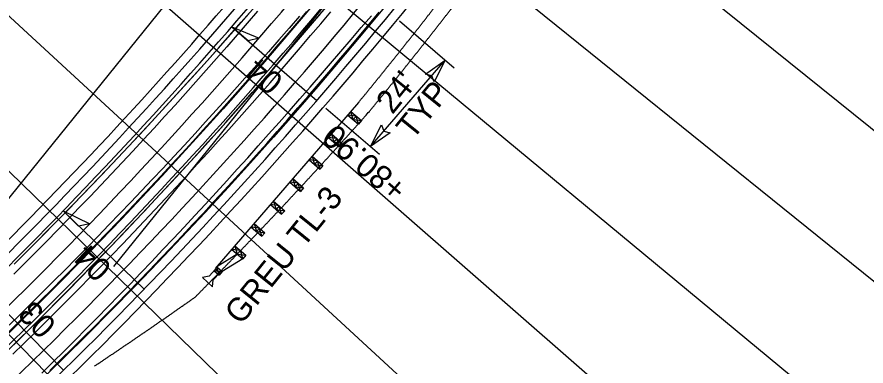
# Model space of a CAD drawing. Extents: x 2293233 to 2294507, y 892788 to 894229.
# Drawn here: x 2293687.7 to 2293868.5, y 893239.9 to 893314.3 of the extents above; entities that cross this region are included whole.
import ezdxf

# ---------------------------------------------------------------- set-up
doc = ezdxf.new("R2010")
doc.units = 0
for name, color, linetype in [('COGO Default Curve', 7, 'Continuous'), ('Prop Dimension', 7, 'Continuous'), ('Prop EOT', 7, 'Continuous'), ('Prop Guardrail', 7, 'Continuous'), ('Prop Guardrail Anchor Unit CELL', 7, 'Continuous'), ('Prop Horizontal Alignment', 7, 'Continuous'), ('Prop Paved Shoulder', 7, 'Continuous'), ('Prop Superelevation  Arrow CELL', 7, 'Continuous'), ('Prop Superelevation Label', 7, 'Continuous'), ('Scratch_Level_4', 7, 'Continuous'), ('Scratch_Level_5', 7, 'Continuous'), ('Typical Terminator CELL', 7, 'Continuous')]:
    doc.layers.add(name, color=color, linetype=linetype)

# ---------------------------------------------------------------- blocks, each defined once
blk = doc.blocks.new('TERMINATOR')
at = {"layer": 'Typical Terminator CELL'}
blk.add_lwpolyline([(-0.469, 0.081), (0, 0), (-0.471, -0.083), (-0.411, 0)], close=True, dxfattribs=at)

msp = doc.modelspace()

# ---------------------------------------------------------------- linework, layer by layer
at = {"layer": 'COGO Default Curve'}
for points in [[(2294073.94, 893697.86), (2293868.79, 893443.63), (2293792.2, 893348.66), (2293779.83, 893333.36), (2293770.79, 893322.25), (2293765.29, 893315.55), (2293760.6, 893309.91), (2293756.09, 893304.55), (2293751.76, 893299.48), (2293746.96, 893293.94), (2293742.34, 893288.69), (2293737.45, 893283.22), (2293732.75, 893278.03), (2293727.78, 893272.64), (2293722.77, 893267.28), (2293717.72, 893261.96), (2293712.86, 893256.92), (2293707.73, 893251.68), (2293702.8, 893246.71), (2293697.59, 893241.55), (2293692.58, 893236.66)], [(2294044.74, 893680.7), (2293954.06, 893568.41), (2293770.67, 893341.16), (2293761.43, 893329.77), (2293756.77, 893324.11), (2293752.51, 893318.98), (2293748.22, 893313.88), (2293744.11, 893309.05), (2293739.98, 893304.26), (2293735.81, 893299.49), (2293731.62, 893294.74), (2293727.39, 893290.03), (2293722.91, 893285.09), (2293718.62, 893280.44), (2293714.3, 893275.81), (2293709.95, 893271.21), (2293705.56, 893266.64), (2293701.15, 893262.1), (2293696.71, 893257.59), (2293692.23, 893253.11), (2293687.73, 893248.66), (2293683.19, 893244.24), (2293678.63, 893239.85)], [(2293680.14, 893237.74), (2293686.34, 893243.78), (2293692.26, 893249.64), (2293698.14, 893255.55), (2293703.96, 893261.51), (2293709.74, 893267.51), (2293715.47, 893273.56), (2293720.92, 893279.42), (2293726.55, 893285.56), (2293732.12, 893291.75), (2293737.87, 893298.24), (2293743.8, 893305.01), (2293749.89, 893312.08), (2293756.38, 893319.69), (2293763.26, 893327.84), (2293770.53, 893336.54), (2293778.4, 893346.03), (2293786.88, 893356.32), (2293796.39, 893367.93), (2293808.61, 893382.91), (2293822.69, 893400.24), (2293860.23, 893446.62), (2293932.89, 893536.61), (2294046.75, 893677.72)], [(2293687.14, 893261.63), (2293692.08, 893266.58), (2293696.99, 893271.57), (2293701.87, 893276.59), (2293706.71, 893281.65), (2293711.51, 893286.74), (2293716.29, 893291.86), (2293721.02, 893297.02), (2293725.73, 893302.2), (2293730.62, 893307.66), (2293735.48, 893313.16), (2293740.31, 893318.68), (2293745.1, 893324.23), (2293750.07, 893330.06), (2293755.02, 893335.92), (2293760.15, 893342.06), (2293765.46, 893348.48), (2293771.17, 893355.44), (2293778.96, 893365), (2293789.02, 893377.44), (2293934.91, 893558.24), (2293982.19, 893616.89)], [(2293749.37, 893315.47), (2293747.21, 893312.92), (2293745.05, 893310.37), (2293742.87, 893307.83), (2293740.69, 893305.29), (2293738.49, 893302.76), (2293736.29, 893300.25), (2293734.08, 893297.73), (2293731.85, 893295.23), (2293729.62, 893292.73), (2293727.38, 893290.24), (2293725.14, 893287.76), (2293722.88, 893285.29), (2293720.61, 893282.82), (2293718.34, 893280.37), (2293716.06, 893277.92), (2293713.76, 893275.48), (2293711.46, 893273.04), (2293709.16, 893270.62), (2293706.84, 893268.2), (2293704.51, 893265.79), (2293702.18, 893263.39), (2293699.83, 893261), (2293697.48, 893258.62), (2293695.12, 893256.24), (2293692.75, 893253.87), (2293690.38, 893251.51), (2293687.99, 893249.16), (2293685.6, 893246.82)], [(2293686.81, 893242.42), (2293689.19, 893244.74), (2293691.56, 893247.06), (2293693.92, 893249.39), (2293696.28, 893251.74), (2293698.62, 893254.08), (2293700.96, 893256.44), (2293703.29, 893258.81), (2293705.61, 893261.18), (2293707.92, 893263.56), (2293710.23, 893265.95), (2293712.52, 893268.35), (2293714.81, 893270.76), (2293717.09, 893273.17), (2293719.36, 893275.59), (2293721.62, 893278.02), (2293723.88, 893280.46), (2293726.12, 893282.91), (2293728.36, 893285.36), (2293730.59, 893287.82), (2293732.81, 893290.29), (2293735.02, 893292.76), (2293737.22, 893295.25), (2293739.41, 893297.74), (2293741.6, 893300.24), (2293743.77, 893302.75), (2293745.94, 893305.26), (2293748.1, 893307.78), (2293750.25, 893310.31), (2293752.39, 893312.85), (2293754.52, 893315.4)], [(2293738.9, 893315.49), (2293736.74, 893312.96), (2293734.57, 893310.45), (2293732.39, 893307.94), (2293730.2, 893305.44), (2293728.01, 893302.95), (2293725.8, 893300.46), (2293723.59, 893297.98), (2293721.37, 893295.52), (2293719.14, 893293.05), (2293716.9, 893290.6), (2293714.65, 893288.16), (2293712.39, 893285.72), (2293710.13, 893283.29), (2293707.86, 893280.87), (2293705.58, 893278.46), (2293703.29, 893276.05), (2293700.99, 893273.66), (2293698.68, 893271.27), (2293696.36, 893268.89), (2293694.04, 893266.52), (2293691.71, 893264.15), (2293689.37, 893261.8), (2293687.02, 893259.45)], [(2293687.02, 893244.44), (2293689.38, 893246.77), (2293691.73, 893249.11), (2293694.08, 893251.46), (2293696.41, 893253.81), (2293698.74, 893256.17), (2293701.07, 893258.53), (2293703.38, 893260.91), (2293705.69, 893263.29), (2293707.99, 893265.68), (2293710.28, 893268.07), (2293712.56, 893270.48), (2293714.84, 893272.89), (2293717.1, 893275.31), (2293719.36, 893277.74), (2293721.61, 893280.17), (2293723.86, 893282.61), (2293726.09, 893285.06), (2293728.32, 893287.52), (2293730.54, 893289.98), (2293732.75, 893292.46), (2293734.96, 893294.93), (2293737.15, 893297.42), (2293739.35, 893299.91), (2293741.53, 893302.41), (2293743.71, 893304.92), (2293745.89, 893307.43), (2293748.06, 893309.95), (2293750.22, 893312.47), (2293752.39, 893314.99)], [(2293737.08, 893314.98), (2293734.89, 893312.49), (2293732.7, 893310), (2293730.49, 893307.52), (2293728.28, 893305.04), (2293726.06, 893302.57), (2293723.84, 893300.11), (2293721.61, 893297.66), (2293719.37, 893295.21), (2293717.12, 893292.77), (2293714.87, 893290.33), (2293712.6, 893287.91), (2293710.34, 893285.49), (2293708.06, 893283.07), (2293705.77, 893280.67), (2293703.48, 893278.27), (2293701.18, 893275.88), (2293698.87, 893273.5), (2293696.56, 893271.13), (2293694.23, 893268.76), (2293691.9, 893266.4), (2293689.56, 893264.05), (2293687.22, 893261.71)], [(2293694.69, 893238.93), (2293697.08, 893241.27), (2293699.46, 893243.62), (2293701.84, 893245.98), (2293704.2, 893248.35), (2293706.56, 893250.73), (2293708.91, 893253.12), (2293711.25, 893255.51), (2293713.58, 893257.91), (2293715.91, 893260.32), (2293718.22, 893262.74), (2293720.53, 893265.16), (2293722.83, 893267.6), (2293725.12, 893270.04), (2293727.4, 893272.49), (2293729.67, 893274.95), (2293731.94, 893277.41), (2293734.19, 893279.89), (2293736.44, 893282.37), (2293738.68, 893284.86), (2293740.91, 893287.35), (2293743.13, 893289.86), (2293745.34, 893292.37), (2293747.55, 893294.89), (2293749.74, 893297.42), (2293751.93, 893299.95), (2293754.1, 893302.5), (2293756.27, 893305.05), (2293758.43, 893307.61), (2293760.58, 893310.17), (2293762.72, 893312.74), (2293764.86, 893315.33)], [(2293747.87, 893314.43), (2293745.68, 893311.9), (2293743.48, 893309.39), (2293741.27, 893306.87), (2293739.06, 893304.37), (2293736.84, 893301.87), (2293734.61, 893299.37), (2293732.38, 893296.88), (2293730.14, 893294.4), (2293727.89, 893291.93), (2293725.63, 893289.46), (2293723.37, 893287), (2293721.09, 893284.55), (2293718.81, 893282.1), (2293716.53, 893279.66), (2293714.23, 893277.23), (2293711.93, 893274.81), (2293709.62, 893272.39), (2293707.3, 893269.98), (2293704.97, 893267.58), (2293702.63, 893265.18), (2293700.29, 893262.8), (2293697.94, 893260.42), (2293695.58, 893258.05), (2293693.21, 893255.68), (2293690.84, 893253.33), (2293688.46, 893250.98), (2293686.07, 893248.64)], [(2293692.98, 893238.38), (2293695.36, 893240.73), (2293697.73, 893243.09), (2293700.09, 893245.45), (2293702.45, 893247.82), (2293704.8, 893250.2), (2293707.14, 893252.59), (2293709.48, 893254.98), (2293711.8, 893257.38), (2293714.12, 893259.79), (2293716.43, 893262.21), (2293718.73, 893264.63), (2293721.03, 893267.07), (2293723.31, 893269.51), (2293725.59, 893271.95), (2293727.86, 893274.41), (2293730.13, 893276.87), (2293732.38, 893279.34), (2293734.62, 893281.82), (2293736.86, 893284.3), (2293739.09, 893286.8), (2293741.31, 893289.29), (2293743.53, 893291.8), (2293745.74, 893294.31), (2293747.94, 893296.82), (2293750.13, 893299.34), (2293752.32, 893301.87), (2293754.5, 893304.4), (2293756.68, 893306.94), (2293758.85, 893309.47), (2293761.02, 893312.02), (2293763.18, 893314.56)]]:
    msp.add_lwpolyline(points, dxfattribs=at)
for radius in [944, 956]:
    msp.add_arc((2293023.75, 893925.54), radius, 308.6085, 321.09608, dxfattribs=at)
at = {"layer": 'Prop Dimension'}
for p, q in [((2293769.15, 893313.47), (2293780.79, 893303.41)), ((2293763.01, 893286.66), (2293778.89, 893305.05)), ((2293753.49, 893294.88), (2293764.9, 893285.02))]:
    msp.add_line(p, q, dxfattribs=at)
at = {"layer": 'Prop EOT'}
for radius, start in [(938, 309.40221), (962, 308.6085)]:
    msp.add_arc((2293023.75, 893925.54), radius, start, 321.09608, dxfattribs=at)
at = {"layer": 'Prop Guardrail'}
msp.add_spline([(2293760.46, 893296.08), (2293760.89, 893296.61), (2293761.33, 893297.14), (2293761.77, 893297.67), (2293762.2, 893298.21), (2293762.64, 893298.74), (2293763.07, 893299.28), (2293763.51, 893299.81), (2293763.94, 893300.35), (2293764.38, 893300.88), (2293764.81, 893301.42), (2293765.24, 893301.95), (2293765.68, 893302.49), (2293766.11, 893303.03), (2293766.54, 893303.56), (2293766.97, 893304.1), (2293767.41, 893304.64), (2293767.84, 893305.18), (2293768.27, 893305.71), (2293768.7, 893306.25), (2293769.13, 893306.79), (2293769.56, 893307.33), (2293769.99, 893307.87), (2293770.41, 893308.41), (2293770.84, 893308.95), (2293771.27, 893309.49), (2293771.7, 893310.03), (2293772.13, 893310.57), (2293772.55, 893311.11), (2293772.98, 893311.65), (2293773.4, 893312.19), (2293773.83, 893312.74), (2293774.25, 893313.28), (2293774.68, 893313.82), (2293775.1, 893314.36), (2293775.53, 893314.91), (2293775.95, 893315.45), (2293776.37, 893315.99), (2293776.8, 893316.54), (2293777.22, 893317.08), (2293777.64, 893317.62), (2293778.05, 893318.15), (2293778.47, 893318.69), (2293778.88, 893319.22), (2293779.29, 893319.76), (2293779.71, 893320.29), (2293780.12, 893320.83), (2293780.53, 893321.36), (2293780.95, 893321.89), (2293781.36, 893322.43), (2293781.78, 893322.96), (2293782.19, 893323.5), (2293782.6, 893324.03), (2293783.02, 893324.57), (2293783.43, 893325.1), (2293783.84, 893325.63), (2293784.26, 893326.17), (2293784.67, 893326.7), (2293785.09, 893327.24), (2293785.5, 893327.77), (2293785.91, 893328.31), (2293786.33, 893328.84), (2293786.74, 893329.37), (2293787.16, 893329.91), (2293787.57, 893330.44), (2293787.98, 893330.98), (2293788.4, 893331.51), (2293788.81, 893332.05), (2293789.22, 893332.58), (2293789.64, 893333.11), (2293790.05, 893333.65), (2293790.47, 893334.18), (2293790.88, 893334.72), (2293791.29, 893335.25), (2293791.71, 893335.79)], degree=3, dxfattribs=at)
at = {"layer": 'Prop Guardrail Anchor Unit CELL'}
for p, q in [((2293760.46, 893296.08), (2293729.94, 893260.66)), ((2293758.8, 893294.15), (2293758.14, 893293.39)), ((2293758.14, 893293.39), (2293760.42, 893291.43)), ((2293758.14, 893293.39), (2293759.28, 893292.41)), ((2293759.93, 893293.17), (2293758.14, 893293.39)), ((2293758.8, 893294.15), (2293761.07, 893292.19)), ((2293759.28, 893292.41), (2293758.8, 893294.15)), ((2293759.93, 893293.17), (2293759.28, 893292.41)), ((2293760.42, 893291.43), (2293759.93, 893293.17)), ((2293759.28, 893292.41), (2293761.07, 893292.19)), ((2293761.07, 893292.19), (2293760.42, 893291.43)), ((2293754.68, 893289.38), (2293757, 893287.38)), ((2293754.68, 893289.38), (2293755.19, 893287.62)), ((2293754.03, 893288.62), (2293756.34, 893286.63)), ((2293755.84, 893288.38), (2293754.03, 893288.62)), ((2293755.84, 893288.38), (2293755.19, 893287.62)), ((2293755.19, 893287.62), (2293757, 893287.38)), ((2293756.34, 893286.63), (2293755.84, 893288.38)), ((2293757, 893287.38), (2293756.34, 893286.63)), ((2293749.92, 893283.84), (2293752.23, 893281.85)), ((2293751.72, 893283.61), (2293749.92, 893283.84)), ((2293750.57, 893284.6), (2293752.88, 893282.61)), ((2293750.57, 893284.6), (2293751.07, 893282.85)), ((2293751.72, 893283.61), (2293751.07, 893282.85)), ((2293751.07, 893282.85), (2293752.88, 893282.61)), ((2293752.23, 893281.85), (2293751.72, 893283.61)), ((2293752.88, 893282.61), (2293752.23, 893281.85)), ((2293746.46, 893279.83), (2293745.8, 893279.07)), ((2293745.8, 893279.07), (2293748.1, 893277.09)), ((2293747.61, 893278.84), (2293745.8, 893279.07)), ((2293746.46, 893279.83), (2293748.76, 893277.85)), ((2293746.46, 893279.83), (2293746.95, 893278.08)), ((2293747.61, 893278.84), (2293746.95, 893278.08)), ((2293748.1, 893277.09), (2293747.61, 893278.84)), ((2293746.95, 893278.08), (2293748.76, 893277.85)), ((2293748.76, 893277.85), (2293748.1, 893277.09)), ((2293742.34, 893275.05), (2293744.72, 893273.01)), ((2293742.34, 893275.05), (2293742.88, 893273.27)), ((2293741.69, 893274.3), (2293744.07, 893272.25)), ((2293743.53, 893274.03), (2293741.69, 893274.3)), ((2293743.53, 893274.03), (2293742.88, 893273.27)), ((2293742.88, 893273.27), (2293744.72, 893273.01)), ((2293744.07, 893272.25), (2293743.53, 893274.03)), ((2293744.72, 893273.01), (2293744.07, 893272.25)), ((2293737.58, 893269.52), (2293739.85, 893267.56)), ((2293739.37, 893269.3), (2293737.58, 893269.52)), ((2293738.23, 893270.28), (2293740.5, 893268.32)), ((2293738.23, 893270.28), (2293738.72, 893268.54)), ((2293739.37, 893269.3), (2293738.72, 893268.54)), ((2293738.72, 893268.54), (2293740.5, 893268.32)), ((2293739.85, 893267.56), (2293739.37, 893269.3)), ((2293740.5, 893268.32), (2293739.85, 893267.56)), ((2293733.47, 893264.75), (2293735.79, 893262.75)), ((2293735.28, 893264.51), (2293733.47, 893264.75)), ((2293734.12, 893265.51), (2293736.44, 893263.51)), ((2293734.12, 893265.51), (2293734.63, 893263.75)), ((2293735.28, 893264.51), (2293734.63, 893263.75)), ((2293735.79, 893262.75), (2293735.28, 893264.51)), ((2293734.63, 893263.75), (2293730.27, 893261.04)), ((2293735.79, 893262.75), (2293731.4, 893260.06)), ((2293734.63, 893263.75), (2293736.44, 893263.51)), ((2293736.44, 893263.51), (2293735.79, 893262.75)), ((2293729.98, 893260.58), (2293728.61, 893259.06)), ((2293730.43, 893260.18), (2293729.98, 893260.58)), ((2293730.27, 893261.04), (2293731.4, 893260.06)), ((2293730.75, 893259.3), (2293730.27, 893261.04)), ((2293728.61, 893259.06), (2293727.19, 893258.75)), ((2293727.19, 893258.75), (2293729.38, 893256.79)), ((2293729.52, 893258.24), (2293730.89, 893259.77)), ((2293729.61, 893260.28), (2293730.75, 893259.3)), ((2293729.61, 893260.28), (2293731.4, 893260.06)), ((2293730.89, 893259.77), (2293730.43, 893260.18)), ((2293731.4, 893260.06), (2293730.75, 893259.3)), ((2293731.4, 893260.06), (2293731.08, 893259.68)), ((2293729.38, 893256.79), (2293729.52, 893258.24))]:
    msp.add_line(p, q, dxfattribs=at)
at = {"layer": 'Prop Horizontal Alignment'}
msp.add_arc((2293023.75, 893925.54), 950, 308.6085, 321.09608, dxfattribs=at)
msp.add_arc((2293023.75, 893925.54), 950, 308.6085, 321.09608, dxfattribs=at)
at = {"layer": 'Prop Paved Shoulder'}
for radius, start in [(936, 310.01837), (964, 308.6085)]:
    msp.add_arc((2293023.75, 893925.54), radius, start, 321.09608, dxfattribs=at)
at = {"layer": 'Prop Superelevation  Arrow CELL'}
for p, q in [((2293733.44, 893312.21), (2293751.6, 893296.51)), ((2293697.53, 893272.96), (2293714.77, 893256.26)), ((2293680.83, 893256.14), (2293697.64, 893239.02))]:
    msp.add_line(p, q, dxfattribs=at)
for points in [[(2293733.44, 893312.21), (2293739.29, 893309.8), (2293736.94, 893309.18)], [(2293697.53, 893272.96), (2293703.23, 893270.22), (2293700.85, 893269.74)]]:
    msp.add_lwpolyline(points, close=True, dxfattribs=at)
at = {"layer": 'Scratch_Level_4'}
for p, q in [((2293708.32, 893261.12), (2294130.82, 893784.65)), ((2293669.61, 893451.99), (2293903.07, 893263.59)), ((2293653.9, 893432.54), (2293887.36, 893244.13)), ((2293639.43, 893414.71), (2293870.31, 893223.16)), ((2293625.77, 893398.69), (2293851.53, 893201.12)), ((2293611.7, 893383.03), (2293832.18, 893179.59)), ((2293597.22, 893367.75), (2293812.28, 893158.58)), ((2293582.35, 893352.85), (2293791.82, 893138.1))]:
    msp.add_line(p, q, dxfattribs=at)
at = {"layer": 'Scratch_Level_5'}
msp.add_line((2293676.84, 893264.33), (2293818.17, 893439.42), dxfattribs=at)
msp.add_arc((2293023.75, 893925.54), 934, 310.67386, 321.09608, dxfattribs=at)
for points in [[(2293762.77, 893294.17), (2293763.21, 893294.71), (2293763.65, 893295.24), (2293764.09, 893295.78), (2293764.53, 893296.31), (2293764.96, 893296.85), (2293765.4, 893297.38), (2293765.84, 893297.92), (2293766.27, 893298.46), (2293766.71, 893298.99), (2293767.14, 893299.53), (2293767.58, 893300.07), (2293768.01, 893300.61), (2293768.45, 893301.14), (2293768.88, 893301.68), (2293769.31, 893302.22), (2293769.75, 893302.76), (2293770.18, 893303.3), (2293770.61, 893303.84), (2293771.04, 893304.38), (2293771.47, 893304.92), (2293771.9, 893305.46), (2293772.33, 893306), (2293772.76, 893306.54), (2293773.19, 893307.08), (2293773.62, 893307.63), (2293774.05, 893308.17), (2293774.48, 893308.71), (2293774.91, 893309.25), (2293775.34, 893309.8), (2293775.76, 893310.34), (2293776.19, 893310.88), (2293776.62, 893311.43), (2293777.04, 893311.97), (2293777.47, 893312.52), (2293777.89, 893313.06), (2293778.32, 893313.61), (2293778.74, 893314.15), (2293779.17, 893314.7), (2293779.59, 893315.24), (2293780.01, 893315.78), (2293780.42, 893316.32), (2293780.84, 893316.85), (2293781.25, 893317.39), (2293781.66, 893317.92), (2293782.08, 893318.45), (2293782.49, 893318.99), (2293782.91, 893319.52), (2293783.32, 893320.06), (2293783.73, 893320.59), (2293784.15, 893321.13), (2293784.56, 893321.66), (2293784.98, 893322.19), (2293785.39, 893322.73), (2293785.8, 893323.26), (2293786.22, 893323.8), (2293786.63, 893324.33), (2293787.04, 893324.87), (2293787.46, 893325.4), (2293787.87, 893325.93), (2293788.29, 893326.47), (2293788.7, 893327), (2293789.11, 893327.54), (2293789.53, 893328.07), (2293789.94, 893328.61), (2293790.35, 893329.14), (2293790.77, 893329.67), (2293791.18, 893330.21), (2293791.6, 893330.74), (2293792.01, 893331.28), (2293792.42, 893331.81), (2293792.84, 893332.35), (2293793.25, 893332.88), (2293793.67, 893333.41), (2293794.08, 893333.95)], [(2293725.66, 893254.59), (2293726.17, 893255.11), (2293726.69, 893255.64), (2293727.2, 893256.16), (2293727.72, 893256.68), (2293728.23, 893257.2), (2293728.75, 893257.72), (2293729.26, 893258.25), (2293729.77, 893258.77), (2293730.29, 893259.29), (2293730.8, 893259.82), (2293731.31, 893260.34), (2293731.82, 893260.87), (2293732.33, 893261.39), (2293732.84, 893261.92), (2293733.36, 893262.44), (2293733.87, 893262.97), (2293734.38, 893263.5), (2293734.88, 893264.03), (2293735.39, 893264.55), (2293735.9, 893265.08), (2293736.41, 893265.61), (2293736.92, 893266.14), (2293737.43, 893266.67), (2293737.93, 893267.2), (2293738.44, 893267.73), (2293738.95, 893268.26), (2293739.45, 893268.79), (2293739.96, 893269.32), (2293740.46, 893269.85), (2293740.97, 893270.38), (2293741.47, 893270.92), (2293741.97, 893271.45), (2293742.48, 893271.98), (2293742.98, 893272.52), (2293743.48, 893273.05), (2293743.99, 893273.58), (2293744.49, 893274.12), (2293744.99, 893274.65), (2293745.49, 893275.19), (2293745.99, 893275.73), (2293746.49, 893276.26), (2293746.99, 893276.8), (2293747.49, 893277.34), (2293747.99, 893277.87), (2293748.49, 893278.41), (2293748.99, 893278.95), (2293749.48, 893279.49), (2293749.98, 893280.03), (2293750.48, 893280.57), (2293750.98, 893281.11), (2293751.47, 893281.65), (2293751.97, 893282.19), (2293752.46, 893282.73), (2293752.96, 893283.27), (2293753.45, 893283.81), (2293753.95, 893284.35), (2293754.44, 893284.89), (2293754.94, 893285.44), (2293755.43, 893285.98), (2293755.92, 893286.52), (2293756.41, 893287.07), (2293756.91, 893287.61), (2293757.4, 893288.16), (2293757.89, 893288.7), (2293758.38, 893289.25), (2293758.87, 893289.79), (2293759.36, 893290.34), (2293759.85, 893290.89), (2293760.34, 893291.43), (2293760.83, 893291.98), (2293761.31, 893292.53), (2293761.8, 893293.08), (2293762.78, 893294.17)], [(2293704.24, 893239.91), (2293704.53, 893240.1), (2293704.82, 893240.29), (2293705.11, 893240.49), (2293705.4, 893240.68), (2293705.69, 893240.88), (2293705.98, 893241.07), (2293706.28, 893241.27), (2293706.57, 893241.46), (2293706.86, 893241.66), (2293707.15, 893241.85), (2293707.44, 893242.05), (2293707.73, 893242.24), (2293708.02, 893242.44), (2293708.31, 893242.63), (2293708.6, 893242.83), (2293708.89, 893243.03), (2293709.18, 893243.22), (2293709.47, 893243.42), (2293709.76, 893243.61), (2293710.05, 893243.81), (2293710.34, 893244.01), (2293710.64, 893244.2), (2293710.93, 893244.4), (2293711.22, 893244.6), (2293711.51, 893244.79), (2293711.8, 893244.99), (2293712.09, 893245.19), (2293712.38, 893245.39), (2293712.67, 893245.58), (2293712.96, 893245.78), (2293713.25, 893245.98), (2293713.54, 893246.18), (2293713.82, 893246.37), (2293714.11, 893246.57), (2293714.4, 893246.77), (2293714.69, 893246.97), (2293714.98, 893247.17), (2293715.27, 893247.37), (2293715.56, 893247.56), (2293715.85, 893247.76), (2293716.14, 893247.96), (2293716.43, 893248.16), (2293716.72, 893248.36), (2293717.01, 893248.56), (2293717.3, 893248.76), (2293717.59, 893248.96), (2293717.88, 893249.16), (2293718.16, 893249.36), (2293718.45, 893249.56), (2293718.74, 893249.76), (2293719.03, 893249.96), (2293719.32, 893250.16), (2293719.61, 893250.36), (2293719.9, 893250.56), (2293720.18, 893250.76), (2293720.47, 893250.96), (2293720.76, 893251.16), (2293721.05, 893251.36), (2293721.34, 893251.56), (2293721.63, 893251.76), (2293721.91, 893251.97), (2293722.2, 893252.17), (2293722.49, 893252.37), (2293722.78, 893252.57), (2293723.07, 893252.77), (2293723.35, 893252.97), (2293723.64, 893253.18), (2293723.93, 893253.38), (2293724.22, 893253.58), (2293724.51, 893253.78), (2293724.79, 893253.99), (2293725.08, 893254.19), (2293725.66, 893254.59)]]:
    msp.add_spline(points, degree=3, dxfattribs=at)

# ---------------------------------------------------------------- block references
at = {"layer": 'Prop Dimension'}
for p, xscale, yscale, rotation in [((2293778.89, 893305.05), 10.604453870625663, 15.220700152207, 49.166048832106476), ((2293763.01, 893286.66), 10.604453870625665, 15.220700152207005, -130.83395116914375)]:
    msp.add_blockref('TERMINATOR', p, dxfattribs=dict(at, xscale=xscale, yscale=yscale, rotation=rotation))

# ---------------------------------------------------------------- texts
for s, rotation, p in [("24'", 51.0748, (2293767.67, 893293.35)), ('TYP', 51.0748, (2293771.98, 893287.93)), ('+80.90', 139.166, (2293771.17, 893278.3))]:
    msp.add_text(s, height=5, rotation=rotation, dxfattribs=at).set_placement(p)
at = {"layer": 'Prop Guardrail Anchor Unit CELL'}
msp.add_text('GREU TL-3', height=5, rotation=51.0748, dxfattribs=at).set_placement((2293735.41, 893248.45))
at = {"layer": 'Prop Superelevation Label'}
for s, rotation, p in [('04', 139.166, (2293744.76, 893301.11)), ('04', 135.9159, (2293708.18, 893261.07)), ('03', 134.4684, (2293696.38, 893248.87))]:
    msp.add_text(s, height=5, rotation=rotation, dxfattribs=at).set_placement(p)

doc.saveas('drawing.dxf')
